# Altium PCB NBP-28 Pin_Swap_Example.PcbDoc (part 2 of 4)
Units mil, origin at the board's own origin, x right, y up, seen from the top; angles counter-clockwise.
Board outline 2716.54 x 4967.15 mil, 10 copper layers (Top Layer, Mid-Layer 1, VCC1V2, Mid-Layer 2, VCC, GND, MidLayer4, VCCINT, Mid-Layer 3, Bottom Layer), stack 81 mil thick; 254 components, 445 nets, 1667 pads, 770 vias.
Unrouted connection lines stored in the file: 611.
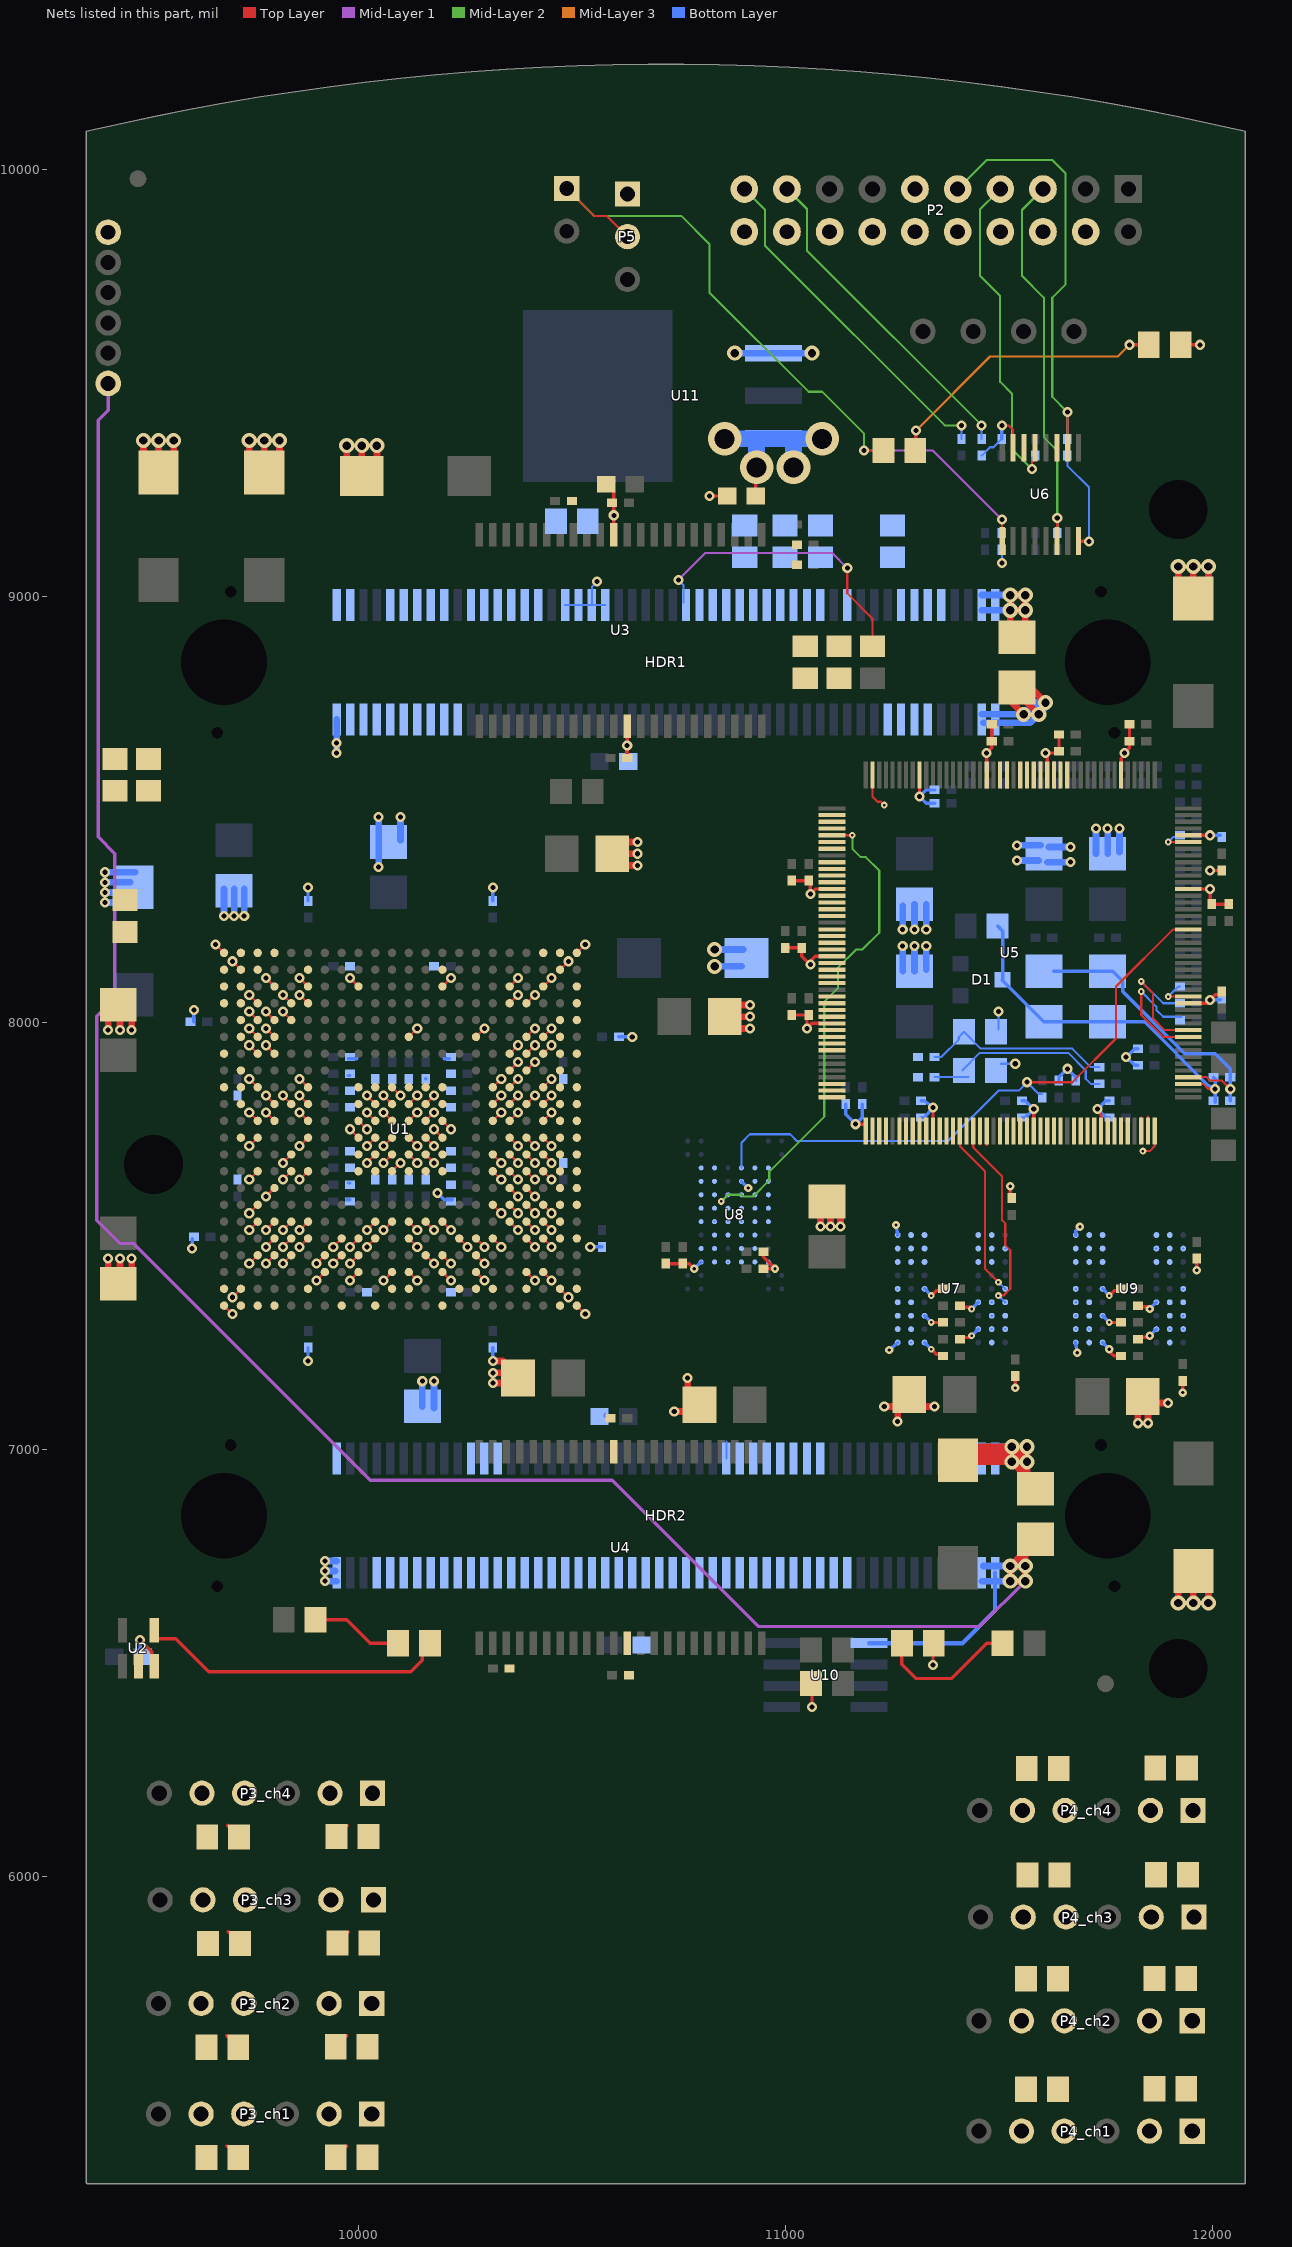
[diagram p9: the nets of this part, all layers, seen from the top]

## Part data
C1: library part CAP-NP-220nF-10V-0603, "Capacitor"
C2 C3 C16 C17 C30 C31 C32: library part CAP-P-10uF-16V-MCCT-B, "Polar Capacitor"
C4 C5 C12 C13 C14 C15 C18 C19 C20 C21 C33 C34 C35 C36 C41 C42: library part CAP-NP-0.1uF-16V-0402, "Capacitor"
C6 C7 C8 C9 C10 C11 C22 C23 C24 C25 C26 C27 C28 C29 C37 C38 C39 C40 C43 C44 C45 C46 C47 C48: library part CAP-NP-10nF-16V-0402, "Capacitor"
C49 C50 C64 C65 C66 C67 C88 C89 C102 C110 C111 C123 C125 C126 C127 C128 C129 C130 C131 C132 C133: library part CAP-P, "Polar Capacitor"
C51 C52 C53 C54 C55 C56 C57 C58 C59 C60 C61 C62 C63 C68 C69 C70 C71 C72 C73 C74 C75 C76 C77 C78 C79 C80 C81 C82 C83 C84 C85 C86 C87 C90 C91 C92 C93 C94 C95 C96 C97 C98 C99 C100 C101 C103 C104 C105 C106 C107 C108 C109 C112 C113 C114 C115 C116 C117 C118 C119 C120 C121 C122 C124: library part CAP-NP, "Capacitor"
D1: library part DIO-SCHOTTKY-1S-SOT23, "Schottky Barrier Double Diode"
HDR1 HDR2: library part CON-DOCKSTAT-M-0.8mm, "Board-to-Board, Docking Station, 0.80mm (.031\") Pitch, Shielded Receptacle, Vertical, Ultra Low Profile, SMT"
LED1: library part LED-RED-HSMHC170, "Typical GREEN SMD LED Agilent make"
LED2: library part LED-GRN-HSMHC170, "Typical GREEN SMD LED Agilent make"
LED3: library part DIO-LED-1S, "Typical GREEN SMD LED Agilent make"
P1: library part CON-HDR-1x2-STR, "Header, 2-Pin"
P2: library part CON-IDC-2x10-M-STR, "10x2 IDC Male PCB Box Header"
P3_ch1 P3_ch2 P3_ch3 P3_ch4 P4_ch1 P4_ch2 P4_ch3 P4_ch4: "Header, 6-Pin"
P5: "Header, 3-Pin"
R1 R15 R17 R18 R19: library part RES-4K7-0402, "Resistor"
R2 R3 R4 R6 R7 R8 R9 R10 R11 R12 R13 R14 R16: library part RES-100R-0805, "Resistor"
R5: library part RES-270R-1%-0805, "Resistor"
R20 R21 R22 R23 R24 R25 R26 R27 R28 R29 R30 R31 R32 R33 R34 R35 R36 R37 R38 R39 R40 R41 R42 R43 R44 R45 R46 R47 R48 R49 R50 R51 R52 R53 R54 R55 R56 R57 R58 R59 R60 R61 R62 R63 R64 R65 R66 R67 R68_ch1 R68_ch2 R68_ch3 R68_ch4 R69_ch1 R69_ch2 R69_ch3 R69_ch4 R70_ch1 R70_ch2 R70_ch3 R70_ch4 R71_ch1 R71_ch2 R71_ch3 R71_ch4: library part RES, "Resistor"
TP1 TP2 TP3 TP4 TP5 TP6 TP7 TP8 TP9 TP10: library part TestPin
U1: "Spartan-3 1.2V FPGA, 333 User I/Os, 456-ball FBGA, Standard Performance, Commercial Grade"
U3 U4: library part K6R4016V1D-T, "256Kx16Bit SRAM TSOP44"
U5: "32-Bit ARM720T-Based BlueStreak MCU with 8KB Cache, MMU, Color LCD controller, 32KB SRAM, 176-Pin LQFP"
U6: library part 74LCX157-TSOP16, "Quad 2-Input Multiplexer"
U7 U9: library part MT48LC16M16A2FG, "256Mb Synchronous High-Speed CMOS DRAM, 16Mb x 16Bit x 4 Banks, 54-Ball FPGA, Commercial"
U8: library part AM29LV640DU90RWHI, "64 Mb (4 M x 16) CMOS 3.0 Volt, Uniform Sector Flash Memory with VersatileI/O Control, 63-ball FBGA, Industrial Grade"
U10: library part VRG-ADJ-8, "Low Current 3-Terminal Adjustable Positive Voltage Regulator"
U11: library part VRG-ADJ-3, "5A Low Dropout Positive Regulators"

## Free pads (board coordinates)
  round 39.37 smd paste-39.37 mask+78.74: FID(9482.69,9978.67) FID(11750.41,6451.11)
  round 39.37 smd far side paste-39.37 mask+78.74: FID(9482.69,9978.67) FID(11750.41,6451.11)
  round 125.98 hole 137.8 unplated mask+3.94: LP(9519.16,7668.29) LP(11920.74,6487.18) LP(11920.74,9203.72)

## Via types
v1: diameter 23.62, hole 11.81, Top Layer to Bottom Layer, 495 vias
v2: diameter 78.74, hole 47.24, Top Layer to Bottom Layer, 101 vias
v3: diameter 15.75, hole 5.91, Top Layer to Bottom Layer, 92 vias
v4: diameter 35.43, hole 19.68, Top Layer to Bottom Layer, 59 vias
v5: diameter 19.68, hole 7.87, Top Layer to Bottom Layer, 23 vias

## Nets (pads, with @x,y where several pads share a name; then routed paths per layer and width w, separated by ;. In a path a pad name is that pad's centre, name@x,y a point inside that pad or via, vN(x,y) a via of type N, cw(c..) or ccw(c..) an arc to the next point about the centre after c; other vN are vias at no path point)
+5V: C123.1 C124.1 C125.1 HDR1.97 HDR1.99 HDR2.97 HDR2.99 TP8.1 U10.1 U11.3 | length 6499.5
  Top Layer w7.87: C124.1@10930.58,9235.22 v2@10930.58,9300.18
  Top Layer w15.75: C123.1@11530.97,8750.96 v4(11558.53,8723.41) ; C123.1@11546.72,8790.33 11546.72,8770.65 v4(11593.96,8723.41) ; C123.1@11558.53,8794.27 11566.41,8794.27 v4(11609.71,8750.96) ; C125.1@11562.47,6786.4 C125.1@11562.47,6762.78 ; v4(11527.04,6727.34) v4(11562.47,6727.34) ; v4(11527.04,6727.34) v4(11527.04,6691.91) v4(11562.47,6691.91) v4(11562.47,6727.34) ; v4(11527.04,6727.34) C125.1@11562.47,6762.78 ; v4(11562.47,6727.34) C125.1@11562.47,6762.78
  Mid-Layer 1 w7.87: TP8.1@9412.86,9499 9412.86,9436 9389.24,9412.38 9389.24,8436 9428.61,8396.63 9428.61,8058.05 9386.36,8015.81 9386.36,7537.3 9440.42,7483.25 9471.92,7483.25 10027.04,6928.13 10593.96,6928.13 10936.48,6585.61 11456.17,6585.61 v4(11562.47,6691.91)
  Bottom Layer w10: U10.1@11196.33,6546.44 11415,6546.44 11491.6,6623.04 11491.6,6691.91 HDR2.99@11491.6,6711.59
  Bottom Layer w15.75: HDR2.97@11460.11,6691.91 11491.6,6691.91 v4(11527.04,6691.91) v4(11562.47,6691.91) ; HDR1.97@11460.11,8723.41 v4(11558.53,8723.41) ; HDR2.97@11464.04,6727.34 v4(11527.04,6727.34) v4(11562.47,6727.34) ; HDR1.97@11464.04,8703.72 11574.28,8703.72 v4(11593.96,8723.41) ; v4@11586.09,8735.22 v4@11601.84,8750.96 ; v4(11558.53,8723.41) v4(11593.96,8723.41) ; v4(11558.53,8723.41) 11586.09,8750.96 v4@11601.84,8750.96 ; v4(11593.96,8723.41) 11609.71,8739.15 v4(11609.71,8750.96) v4@11601.84,8750.96
  Bottom Layer w39.37: v2(10857.74,9369.07) U11.3@10932.55,9369.07 ; v2(10932.55,9302.15) U11.3@10932.55,9369.07 ; v2(11019.16,9302.15) U11.3@11019.16,9369.07 ; v2(11086.09,9369.07) U11.3@11019.16,9369.07 ; U11.3@10932.55,9369.07 U11.3@11019.16,9369.07
A0: U1.H2 U5.32 U7.H7 U9.H7 | length 2.1
  Bottom Layer w5: U9.H7@11867.43,7471.44 U9.H7@11869.56,7471.44
A1: U1.R19 U5.31 U7.H8 U8.G2 U9.H8 | length 27.8
  Top Layer w5: U1.R19@10393.18,7613.17 v1(10412.86,7593.48)
A2: U1.P19 U5.30 U7.J8 U8.F2 U9.J8 | length 27.8
  Top Layer w5: U1.P19@10393.18,7652.54 v1(10412.86,7632.85)
A3: U1.N18 U5.29 U7.J7 U8.E2 U9.J7 | length 27.8
  Top Layer w5: U1.N18@10353.81,7691.91 v1(10373.49,7672.22)
A4: U1.K17 U5.27 U7.J3 U8.C2 U9.J3 | length 27.8
  Top Layer w5: U1.K17@10314.44,7810.02 v1(10334.12,7829.71)
A5: U1.N21 U5.26 U7.J2 U8.D2 U9.J2
A6: U1.P18 U5.25 U7.H3 U8.F3 U9.H3 | length 27.8
  Top Layer w5: U1.P18@10353.81,7652.54 v1(10373.49,7632.85)
A7: U1.P22 U5.24 U7.H2 U8.E3 U9.H2
A8: U1.L20 U5.22 U7.H1 U8.C3 U9.H1 | length 27.8
  Top Layer w5: U1.L20@10432.55,7770.65 v1(10452.23,7790.34)
A9: U1.N20 U5.21 U7.G3 U8.D6 U9.G3 | length 27.8
  Top Layer w5: U1.N20@10432.55,7691.91 v1(10452.23,7672.22)
A10: U1.K4 U5.20 U7.H9 U8.C6 U9.H9 | length 27.8
  Top Layer w5: v1(9782.94,7829.71) U1.K4@9802.63,7810.02
A11: U1.M2 U5.19 U7.G2 U8.E6 U9.G2
A12: U1.N5 U5.17 U7.G1 U8.F6 U9.G1 | length 27.8
  Top Layer w5: v1(9822.31,7672.22) U1.N5@9842,7691.91
A13: U1.N17 U5.16 U7.G7 U8.D7 U9.G7 | length 27.8
  Top Layer w5: U1.N17@10314.44,7691.91 v1(10334.12,7672.22)
A14: U1.N22 U5.15 U7.G8 U8.C7 U9.G8
A15: U1.M6 U5.14 U8.E7 | length 27.8
  Top Layer w5: v1(9861.68,7711.59) U1.M6@9881.37,7731.28
A16: U1.P17 U5.12 U8.F7 | length 27.8
  Top Layer w5: U1.P17@10314.44,7652.54 v1(10334.12,7632.85)
A17: U1.T19 U5.11 U8.G7 | length 27.8
  Top Layer w5: U1.T19@10393.18,7573.8 v1(10412.86,7554.11)
A18: U1.M18 U5.10 U8.D3 | length 27.8
  Top Layer w5: U1.M18@10353.81,7731.28 v1(10373.49,7711.59)
A19: U1.P21 U5.9 U8.E4
A20: U1.R21 U5.7 U8.F5
A21: U1.R22 U5.6 U8.F4
A22: U1.N19 U5.5 U8.E5 | length 1190.8
  Top Layer w5: U1.N19@10393.18,7691.91 v1(10412.86,7672.22) ; U5.5@11109.71,8439.94 v3(11156.96,8439.94)
  Mid-Layer 2 w5: v3(10849.87,7581.67) 10865.62,7597.42 10897.11,7597.42 10901.05,7593.48 10924.67,7593.48 10962.23,7631.04 10962.23,7651.45 11091.21,7780.43 11091.21,8049.6 11123.02,8081.41 11123.02,8129.48 11165.76,8172.22 11180.58,8172.22 11219.95,8211.59 11219.95,8357.26 11188.45,8388.76 11176.64,8388.76 11156.96,8408.44 v3(11156.96,8439.94)
  Bottom Layer w5: v3(10849.87,7581.67) U8.E5@10865.62,7597.42
A23: U1.F16 U5.4 | length 27.8
  Top Layer w5: U1.F16@10275.07,7967.5 v1(10294.75,7987.19)
A24: U1.D18 U5.3 | length 27.8
  Top Layer w5: U1.D18@10353.81,8046.24 v1(10373.49,8065.93)
A25: U1.F12 U5.2 | length 27.8
  Top Layer w5: U1.F12@10117.59,7967.5 v1(10137.27,7987.19)
AUDIO_SPI_CSN: HDR1.11 U1.F2
BLUE0: HDR1.14 U1.D3 | length 27.8
  Top Layer w5: v1(9743.57,8065.93) U1.D3@9763.26,8046.24
BLUE1: HDR1.16 U1.A4
BOC_CTS: HDR1.13 U1.F4 | length 27.8
  Top Layer w5: v1(9782.94,7987.19) U1.F4@9802.63,7967.5
BOC_RTS: HDR1.17 U1.E5 | length 27.8
  Top Layer w5: v1(9822.31,8026.56) U1.E5@9842,8006.87
BOC_RX: HDR1.19 U1.D6 | length 27.8
  Top Layer w5: v1(9861.68,8065.93) U1.D6@9881.37,8046.24
BOC_TX: HDR1.15 U1.D5 | length 27.8
  Top Layer w5: v1(9822.31,8065.93) U1.D5@9842,8046.24
BUZZER: HDR2.24 U1.W8 | length 27.8
  Top Layer w5: v1(9940.42,7436) U1.W8@9960.11,7455.69
CAN_RXD: HDR1.4 U1.D1
CAN_TXD: HDR1.2 U1.C1
CLK_RTC: R44.2 U1.J18 | length 27.8
  Top Layer w5: U1.J18@10353.81,7849.39 v1(10373.49,7869.08)
CLKIN: R36.2 U1.J17 | length 27.8
  Top Layer w5: U1.J17@10314.44,7849.39 v1(10334.12,7869.08)
CLKOUT: U1.D22 U5.156
D0: U1.R18 U5.87 U8.G3 U9.A8 | length 60.9
  Top Layer w5: U1.R18@10353.81,7613.17 v1(10373.49,7593.48) ; U5.87@11849.87,7747.03 11849.87,7780.13
D1: U1.V22 U5.86 U8.K3 U9.B9 | length 31.5
  Top Layer w5: U5.86@11834.12,7747.03 U5.86@11834.12,7778.52
D2: U1.T22 U5.84 U8.G4 U9.B8 | length 0
D3: U1.V21 U5.83 U8.K4 U9.C9 | length 0
D4: U1.U14 U5.82 U8.K5 U9.C8 | length 27.8
  Top Layer w5: U1.U14@10196.33,7534.43 v1(10216.01,7514.74)
D5: U1.T21 U5.81 U8.G5 U9.D9 | length 0
D6: U1.V20 U5.79 U8.K6 U9.D8 | length 27.8
  Top Layer w5: U1.V20@10432.55,7495.06 v1(10452.23,7475.37)
D7: U1.T20 U5.78 U8.G6 U9.E9 | length 27.8
  Top Layer w5: U1.T20@10432.55,7573.8 v1(10452.23,7554.11)
D8: U1.T18 U5.77 U8.H3 U9.E1 | length 27.8
  Top Layer w5: U1.T18@10353.81,7573.8 v1(10373.49,7554.11)
D9: U1.U20 U5.76 U8.J3 U9.D2 | length 27.8
  Top Layer w5: U1.U20@10432.55,7534.43 v1(10452.23,7514.74)
D10: U1.T17 U5.74 U8.H4 U9.D1 | length 27.8
  Top Layer w5: U1.T17@10314.44,7573.8 v1(10334.12,7554.11)
D11: U1.U19 U5.73 U8.J4 U9.C2 | length 27.8
  Top Layer w5: U1.U19@10393.18,7534.43 v1(10412.86,7514.74)
D12: U1.R4 U5.72 U8.H5 U9.C1 | length 27.8
  Top Layer w5: v1(9782.94,7593.48) U1.R4@9802.63,7613.17
D13: U1.P6 U5.71 U8.J6 U9.B2 | length 27.8
  Top Layer w5: v1(9861.68,7632.85) U1.P6@9881.37,7652.54
D14: U1.U21 U5.69 U8.H6 U9.B1 | length 0
D15: U1.U18 U5.68 U8.J7 U9.A2 | length 27.8
  Top Layer w5: U1.U18@10353.81,7534.43 v1(10373.49,7514.74)
D16: U1.K19 U5.67 U7.A8 | length 27.8
  Top Layer w5: U1.K19@10393.18,7810.02 v1(10412.86,7829.71)
D17: U1.M22 U5.66 U7.B9 | length 0
D18: U1.K22 U5.65 U7.B8 | length 0
D19: U1.M19 U5.63 U7.C9 | length 60.9
  Top Layer w5: U1.M19@10393.18,7731.28 v1(10412.86,7711.59) ; 11471.92,7713.93 U5.63@11471.92,7747.03
D20: U1.K21 U5.62 U7.C8 | length 31.5
  Top Layer w5: 11456.17,7715.53 U5.62@11456.17,7747.03
D21: U1.J2 U5.61 U7.D9 | length 462.3
  Top Layer w5: U5.61@11440.42,7747.03 11440.42,7708.38 11507.35,7641.45 11507.35,7538.37 11515.22,7530.49 11515.22,7479.31 11527.04,7467.5 11527.04,7376.95 11511.29,7361.2 v3(11499.48,7361.2)
  Bottom Layer w5: v3(11499.48,7361.2) U7.D9@11515.22,7345.45
D22: U1.K6 U5.60 U7.D8 | length 27.8
  Top Layer w5: v1(9861.68,7829.71) U1.K6@9881.37,7810.02
D23: U1.M20 U5.59 U7.E9 | length 441.9
  Top Layer w5: U1.M20@10432.55,7731.28 v1(10452.23,7711.59) ; U5.59@11408.93,7747.03 11408.93,7711.59 11467.98,7652.54 11467.98,7424.19 v3(11499.48,7392.7)
  Bottom Layer w5: v3(11499.48,7392.7) U7.E9@11515.22,7376.95
D24: U1.V19 U5.58 U7.E1 | length 27.8
  Top Layer w5: U1.V19@10393.18,7495.06 v1(10412.86,7475.37)
D25: U1.K5 U5.57 U7.D2 | length 27.8
  Top Layer w5: v1(9822.31,7829.71) U1.K5@9842,7810.02
D26: U1.K18 U5.56 U7.D1 | length 27.8
  Top Layer w5: U1.K18@10353.81,7810.02 v1(10373.49,7829.71)
D27: U1.L18 U5.54 U7.C2 | length 27.8
  Top Layer w5: U1.L18@10353.81,7770.65 v1(10373.49,7790.34)
D28: U1.L17 U5.53 U7.C1 | length 27.8
  Top Layer w5: U1.L17@10314.44,7770.65 v1(10334.12,7790.34)
D29: U1.K2 U5.52 U7.B2
D30: U1.M21 U5.51 U7.B1 | length 3.3
  Top Layer w5: U5.51@11280.64,7744.72 U5.51@11282.94,7747.03
D31: U1.L22 U5.50 U7.A2 | length 0
DEBUG_TCK: P2.9 R63.2 U6.10 | length 1026.9
  Top Layer w5: U6.10@11660.89,9349.39 v1(11660.89,9432.07)
  Mid-Layer 2 w5: P2.9@11403.81,9954.51 11471.92,10022.62 11625.46,10022.62 11656.96,9991.12 11656.96,9731.28 11625.46,9699.78 11625.46,9467.5 v1(11660.89,9432.07)
  Bottom Layer w5: R63.2@11660.89,9369.07 v1(11660.89,9432.07)
DEBUG_TDI: P2.5 R61.2 U6.6 | length 915.7
  Top Layer w5: U6.6@11637.27,9128.92 v1(11637.27,9184.04)
  Mid-Layer 2 w5: P2.5@11603.81,9954.51 11554.59,9905.3 11554.59,9750.96 11605.78,9699.78 11605.78,9373.01 11637.27,9341.52 v1(11637.27,9184.04)
  Bottom Layer w5: R61.2@11637.27,9148.6 v1(11637.27,9184.04)
DEBUG_TMS: P2.7 R62.2 U6.13 | length 768.8
  Top Layer w5: v1(11578.22,9298.21) 11578.22,9313.96 U6.13@11586.09,9321.83
  Mid-Layer 2 w5: P2.7@11495.18,9945.88 11456.17,9906.87 11456.17,9750.96 11503.41,9703.72 11503.41,9502.93 11530.97,9475.37 11530.97,9345.45 v1(11578.22,9298.21)
  Bottom Layer w5: v1(11578.22,9298.21) R62.2@11578.22,9325.77
DEOT0: U1.F21 U5.148
DIFF_RX_ch1_N: P3_ch1.5 P4_ch1.1 R69_ch1.2 R71_ch1.1
DIFF_RX_ch1_P: P3_ch1.4 P4_ch1.2 R69_ch1.1 R71_ch1.2 | length 38.7
  Top Layer w7.87: 9690.46,5368.14 R71_ch1.2@9717.86,5340.74
DIFF_RX_ch2_N: P3_ch2.5 P4_ch2.1 R69_ch2.2 R71_ch2.1
DIFF_RX_ch2_P: P3_ch2.4 P4_ch2.2 R69_ch2.1 R71_ch2.2 | length 38.7
  Top Layer w7.87: 9690.46,5626.94 R71_ch2.2@9717.86,5599.54
DIFF_RX_ch3_N: P3_ch3.5 P4_ch3.1 R69_ch3.2 R71_ch3.1
DIFF_RX_ch3_P: P3_ch3.4 P4_ch3.2 R69_ch3.1 R71_ch3.2 | length 38.7
  Top Layer w7.87: 9694.39,5869.98 R71_ch3.2@9721.79,5842.58
DIFF_RX_ch4_N: P3_ch4.5 P4_ch4.1 R69_ch4.2 R71_ch4.1
DIFF_RX_ch4_P: P3_ch4.4 P4_ch4.2 R69_ch4.1 R71_ch4.2 | length 38.7
  Top Layer w7.87: 9692.43,6119.92 R71_ch4.2@9719.83,6092.52
DIFF_TX_ch1_N: P3_ch1.2 P4_ch1.5 R68_ch1.1 R70_ch1.1 | length 36.3
  Top Layer w7.87: R70_ch1.1@9946.13,5341.73 9971.82,5367.42
DIFF_TX_ch1_P: P3_ch1.1 P4_ch1.4 R68_ch1.2 R70_ch1.2
DIFF_TX_ch2_N: P3_ch2.2 P4_ch2.5 R68_ch2.1 R70_ch2.1 | length 36.3
  Top Layer w7.87: R70_ch2.1@9946.13,5600.52 9971.82,5626.22
DIFF_TX_ch2_P: P3_ch2.1 P4_ch2.4 R68_ch2.2 R70_ch2.2
DIFF_TX_ch3_N: P3_ch3.2 P4_ch3.5 R68_ch3.1 R70_ch3.1 | length 36.3
  Top Layer w7.87: R70_ch3.1@9950.06,5843.57 9975.76,5869.26
DIFF_TX_ch3_P: P3_ch3.1 P4_ch3.4 R68_ch3.2 R70_ch3.2
DIFF_TX_ch4_N: P3_ch4.2 P4_ch4.5 R68_ch4.1 R70_ch4.1 | length 36.3
  Top Layer w7.87: R70_ch4.1@9948.09,6093.5 9973.79,6119.2
DIFF_TX_ch4_P: P3_ch4.1 P4_ch4.4 R68_ch4.2 R70_ch4.2
DREQ0: U1.G21 U5.146
FLASH_BUSY: R20.1 U5.114 U8.C4 | length 1444.8
  Top Layer w5: v1(11566.41,7861.2) 11672.7,7861.2 11775.07,7963.56 11775.07,8085.61 11908.93,8219.47 U5.114@11944.36,8219.47
  Bottom Layer w5: U8.C4@10897.11,7660.41 10897.11,7719.47 10916.8,7739.15 11011.29,7739.15 11027.04,7723.41 11381.37,7723.41 11499.48,7841.52 11546.72,7841.52 v1(11566.41,7861.2) 11593.96,7833.64 R20.1@11601.84,7833.64
FPGA_AUX0: R14.1 U1.B3
FPGA_AUX0_R: HDR1.86 R14.2
FPGA_AUX1: HDR1.88 U1.C18 | length 27.8
  Top Layer w5: U1.C18@10353.81,8085.61 v1(10373.49,8105.3)
FPGA_AUX2: HDR1.90 U1.C20 | length 27.8
  Top Layer w5: U1.C20@10432.55,8085.61 v1(10452.23,8105.3)
FPGA_AUX3: HDR1.92 U1.D19 | length 27.8
  Top Layer w5: U1.D19@10393.18,8046.24 v1(10412.86,8065.93)
FPGA_CCLK: R3.2 U1.AA22
FPGA_CCLK_R: HDR1.66 R3.1
FPGA_CLK: HDR2.2 U1.AA11
FPGA_CLK_1: HDR1.30 U1.F3 | length 27.8
  Top Layer w5: v1(9743.57,7987.19) U1.F3@9763.26,7967.5
FPGA_CLK_2: HDR1.32 U1.G4 | length 27.8
  Top Layer w5: v1(9782.94,7947.82) U1.G4@9802.63,7928.13
FPGA_DIN: HDR1.64 U1.B14
FPGA_DONE: R4.2 R15.1 U1.AB21 U2.2
FPGA_DONE_R: HDR1.74 R4.1
FPGA_INIT: HDR1.68 R18.1 R19.1
FPGA_M0: R8.2 U1.AB2
FPGA_M0_R: HDR1.60 R8.1
FPGA_M1: R9.2 U1.AA1
FPGA_M1_R: HDR1.58 R9.1
FPGA_M2: R10.2 U1.AB3
FPGA_M2_R: HDR1.56 R10.1
FPGA_PROGRAM_R: HDR1.62 R7.1 R17.1
FPGA_PROGRAMP: R7.2 U1.A2
FPGA_TCK: HDR1.72 R12.1 U6.11
FPGA_TCKP: R12.2 U1.A21
FPGA_TDI: HDR1.78 R11.1
FPGA_TDIP: R11.2 U1.B1
FPGA_TDO: HDR1.54 R6.2 | length 702.1
  Top Layer w5: v1(11145.15,9065.92) 11145.15,9006.87 11204.2,8947.81 R6.2@11204.2,8882.85
  Mid-Layer 1 w5: v1(10749.3,9038.31) 10812.34,9101.36 11109.71,9101.36 v1(11145.15,9065.92)
  Bottom Layer w5: v1(10749.3,9038.31) 10761.3,9026.31 HDR1.54@10761.3,8985.31
FPGA_TMS: HDR1.70 R13.1 U6.14
FPGA_TMSP: R13.2 U1.A20
GND: C1.1 C2.2 C3.2 C4.2 C5.2 C6.2 C7.2 C8.2 C9.2 C10.2 C11.2 C12.2 C13.2 C14.2 C15.2 C16.2 C17.2 C18.2 C19.2 C20.2 C21.2 C22.2 C23.2 C24.2 C25.2 C26.2 C27.2 C28.2 C29.2 C30.2 C31.2 C32.2 C33.2 C34.2 C35.2 C36.2 C37.2 C38.2 C39.2 C40.2 C41.2 C42.2 C43.2 C44.2 C45.2 C46.2 C47.2 C48.2 C49.2 C50.2 C51.2 C52.2 C53.2 C54.2 C55.2 C56.2 C57.2 C58.2 C62.2 C66.2 C67.2 C68.2 C69.2 C70.2 C71.2 C72.2 C73.2 C74.2 C75.2 C76.2 C77.2 C78.2 C79.2 C80.2 C81.2 C82.2 C83.2 C84.2 C85.2 C86.2 C87.2 C88.2 C89.2 C90.2 C91.2 C92.2 C93.2 C94.2 C95.2 C96.2 C97.2 C98.2 C99.2 C100.2 C101.2 C102.2 C103.2 C104.2 C105.2 C106.2 C107.2 C108.2 C109.2 C110.2 C111.2 C112.2 C113.2 C114.2 C115.2 C116.2 C117.2 C118.2 C119.2 C120.2 C121.2 C122.2 C123.2 C124.2 C125.2 C126.2 C127.2 C128.2 C129.2 C130.2 C131.2 C132.2 C133.2 HDR1.1 HDR1.36 HDR1.38 HDR1.40 HDR1.42 HDR1.98 HDR1.100 HDR2.1 HDR2.98 HDR2.100 LED1.2 LED3.2 P2.4 P2.6 P2.8 P2.10 P2.11 P2.12 P2.14 P2.16 P2.18 P2.20 P5.1 R37.1 R46.1 R60.2 R63.1 R65.2 R66.1 TP10.1 U1.A1 U1.A22 U1.AA2 U1.AA21 U1.AB1 U1.AB22 U1.B2 U1.B21 U1.C9 U1.C14 U1.J3 U1.J9 U1.J10 U1.J11 U1.J12 U1.J13 U1.J14 U1.J20 U1.K9 U1.K10 U1.K11 U1.K12 U1.K13 U1.K14 U1.L9 U1.L10 U1.L11 U1.L12 U1.L13 U1.L14 U1.M9 U1.M10 U1.M11 U1.M12 U1.M13 U1.M14 U1.N9 U1.N10 U1.N11 U1.N12 U1.N13 U1.N14 U1.P3 U1.P9 U1.P10 U1.P11 U1.P12 U1.P13 U1.P14 U1.P20 U1.Y9 U1.Y14 U2.3 U3.12 U3.34 U4.12 U4.34 U5.13 U5.23 U5.33 U5.45 U5.55 U5.70 U5.80 U5.88 U5.103 U5.120 U5.128 U5.138 U5.149 U5.158 U5.168 U5.175 U6.8 U6.15 U7.A1 U7.A3 U7.B7 U7.C3 U7.D7 U7.E3 U7.J1 U8.D4 U8.K2 U8.K7 U9.A1 U9.A3 U9.B7 U9.C3 U9.D7 U9.E3 U9.J1 U11.1 | length 11663.4
  Top Layer w5: v1(9664.83,8184.04) U1.A1@9684.52,8164.35 ; U1.AB1@9684.52,7337.58 v1(9704.2,7317.89) ; v1(9704.2,7357.26) U1.AA2@9723.89,7376.95 ; v1(9704.2,8144.67) U1.B2@9723.89,8124.98 ; v1(9743.57,7632.85) U1.P3@9763.26,7652.54 ; v1(9743.57,7869.08) U1.J3@9763.26,7849.39 ; v1(9979.79,7396.63) U1.Y9@9999.48,7416.32 ; v1(9979.79,7750.97) U1.M9@9999.48,7731.28 ; v1(9979.79,8105.3) U1.C9@9999.48,8085.61 ; U1.L9@9999.48,7770.65 v1(10019.16,7750.96) ; v1(10019.16,7672.22) U1.N10@10038.85,7691.91 ; v1(10019.16,7711.59) U1.M10@10038.85,7731.28 ; v1(10019.16,7790.34) U1.L10@10038.85,7770.65 ; v1(10019.16,7829.71) U1.K10@10038.85,7810.02 ; v1(10058.53,7672.22) U1.N11@10078.22,7691.91 ; v1(10058.53,7711.59) U1.M11@10078.22,7731.28 ; v1(10058.53,7790.34) U1.L11@10078.22,7770.65 ; v1(10058.53,7829.71) U1.K11@10078.22,7810.02 ; U1.P11@10078.22,7652.54 v1(10097.9,7672.23) ; U1.J11@10078.22,7849.39 v1(10097.9,7829.7) ; U1.N12@10117.59,7691.91 v1(10137.27,7672.22) ; U1.M12@10117.59,7731.28 v1(10137.27,7711.59) ; U1.L12@10117.59,7770.65 v1(10137.27,7790.34) ; U1.K12@10117.59,7810.02 v1(10137.27,7829.71) ; U1.N13@10156.96,7691.91 v1(10176.64,7672.22) ; U1.M13@10156.96,7731.28 v1(10176.64,7711.59) ; U1.L13@10156.96,7770.65 v1(10176.64,7790.34) ; U1.K13@10156.96,7810.02 v1(10176.64,7829.71) ; v1(10176.64,7750.97) U1.M14@10196.33,7731.28 ; U1.Y14@10196.33,7416.32 v1(10216.01,7396.63) ; U1.L14@10196.33,7770.65 v1(10216.01,7750.96) ; U1.C14@10196.33,8085.61 v1(10216.01,8105.3) ; U1.P20@10432.55,7652.54 v1(10452.23,7632.85) ; U1.J20@10432.55,7849.39 v1(10452.23,7869.08) ; U1.AA21@10471.92,7376.95 v1(10491.6,7357.26) ; U1.B21@10471.92,8124.98 v1(10491.6,8144.67) ; U1.AB22@10511.29,7337.58 v1(10530.97,7317.89) ; U1.A22@10511.29,8164.35 v1(10530.97,8184.04) ; U5.175@11204.2,8581.67 11204.2,8530.49 11216.01,8518.68 11223.89,8518.68 v3(11231.76,8510.81) ; v1(11507.35,9400.57) 11523.1,9400.57 11533.93,9389.74 U6.15@11533.93,9348.41 ; v3(11838.06,7699.78) 11853.81,7699.78 11865.62,7711.59 U5.88@11865.62,7747.03
  Top Layer w7.87: v1(9487.67,6554.11) 9515.22,6526.55 U2.3@9515.22,6495.06 ; U3.34@10597.9,9139.74 v1(10597.9,9189.94) 10597.9,9262.78 C51.2@10597.9,9270.65 ; C53.2@10629.4,8621.04 v1(10629.4,8650.57) U3.12@10629.4,8695.85 U3.12@10629.4,8700.77 ; C105.2@10719.95,7436 10775.07,7436 v5(10786.88,7424.19) ; v1(10822.31,9235.22) C124.2@10863.65,9235.22 ; C103.2@10948.3,7424.19 v5(10975.85,7424.19) 10948.3,7451.75 C106.2@10948.3,7463.56 ; C71.2@10999.48,8176.16 C81.2@11038.85,8176.16 11038.85,8156.48 v1(11058.53,8136.79) 11058.53,8144.67 11070.34,8156.48 U5.23@11109.71,8156.48 ; C70.2@11015.22,8018.68 C80.2@11054.59,8018.68 ; C68.2@11015.22,8333.64 C78.2@11054.59,8333.64 ; C80.2@11058.53,8014.74 11054.6,8014.74 11050.66,8014.74 v1(11050.66,7987.18) 11062.47,7999 U5.33@11109.71,7999 ; C78.2@11058.53,8329.7 v1(11058.53,8302.15) 11070.34,8313.96 U5.13@11109.71,8313.96 ; v1(11062.47,6396.63) R65.2@11062.47,6449.78 ; v1(11164.83,7762.78) U5.45@11188.45,7762.78 ; v1(11314.44,8530.49) U5.168@11314.44,8581.67 ; v3(11342,7235.22) 11353.81,7223.41 C120.2@11373.49,7223.41 ; v3(11342,7298.21) C118.2@11369.56,7298.21 ; v3(11342,7361.2) 11353.81,7373.01 C109.2@11373.49,7373.01 ; v1(11345.93,6495.06) LED1.2@11345.93,6544.27 ; U5.55@11345.93,7747.03 v1(11345.93,7802.15) ; C119.2@11404.99,7262.78 11432.55,7262.78 v3(11436.48,7266.71) ; C121.2@11404.99,7333.64 11432.55,7333.64 v3(11436.48,7329.7) ; U5.158@11471.92,8581.67 v1(11471.92,8632.85) 11483.73,8644.67 C95.2@11483.73,8699.78 ; C122.2@11527.04,7593.48 v5(11527.04,7617.11) ; v5(11538.85,7144.67) C108.2@11538.85,7172.22 ; U5.70@11582.15,7747.03 v1(11582.15,7798.21) ; v1(11609.71,8632.85) C86.2@11637.27,8632.85 ; U5.149@11613.65,8581.67 v1@11613.65,8628.92 ; C86.2@11641.21,8636.79 C76.2@11641.21,8676.16 ; U6.8@11688.45,9128.92 v1(11712.08,9128.92) ; v1@11731.76,7794.27 11739.63,7786.4 U5.80@11739.63,7747.03 ; v5@11758.33,7232.28 11770.14,7220.47 C117.2@11789.82,7220.47 ; v3(11759.32,7298.21) C112.2@11786.88,7298.21 ; v3(11759.32,7361.2) 11771.13,7373.01 C107.2@11790.82,7373.01 ; U5.138@11786.88,8581.67 11786.88,8621.04 v1@11794.75,8628.92 ; v1(11794.75,8632.85) 11806.56,8644.67 C94.2@11806.56,8699.78 ; C115.2@11821.32,7263.78 11848.88,7263.78 v5@11852.81,7267.71 ; C116.2@11821.32,7334.64 11848.88,7334.64 v5@11852.82,7330.7 ; LED3.2@11926.64,9589.55 v1(11971.92,9589.55) ; v5(11931.56,7133.85) C114.2@11931.56,7161.41 ; U5.103@11944.36,8046.24 11987.67,8046.24 v1(11995.54,8054.11) 12007.35,8065.93 C84.2@12023.1,8065.93 ; U5.120@11944.36,8313.96 v1(11995.54,8313.96) C101.2@11995.54,8282.46 ; U5.128@11944.36,8439.94 v1(11995.54,8439.94) ; v5(11964.04,7420.26) C113.2@11964.04,7447.81 ; v1(11995.54,8357.26) C75.2@12023.1,8357.26 ; C101.2@11999.48,8278.52 C93.2@12038.85,8278.52
  Top Layer w15.75: C3.2@9404.99,7384.82 9412.86,7388.76 v1(9412.86,7447.81) ; C32.2@9404.99,8046.24 9412.86,8042.3 v1(9412.86,7983.25) ; C3.2@9436.48,7384.82 9440.42,7388.76 v1(9440.42,7447.81) ; C32.2@9436.48,8046.24 9440.42,8042.3 v1(9440.42,7983.25) ; C3.2@9467.98,7384.82 v1(9467.98,7447.81) ; v1(9467.98,7983.25) C32.2@9467.98,8046.24 ; C130.2@9495.54,9294.27 v4(9495.54,9365.14) ; C130.2@9530.97,9290.33 v4(9530.97,9365.14) ; C130.2@9566.41,9286.4 v4(9566.41,9365.14) ; C127.2@9743.57,9302.15 v4(9743.57,9365.14) ; C127.2@9779,9290.33 v4(9779,9365.14) ; C127.2@9814.44,9306.08 v4(9814.44,9365.14) ; C131.2@9971.92,9282.46 v4(9971.92,9353.33) ; C131.2@10007.35,9282.46 v4(10007.35,9353.33) ; C131.2@10042.78,9282.46 v4(10042.78,9353.33) ; v1(10314.44,7156.48) C2.2@10373.49,7156.48 ; v1(10314.44,7180.1) C2.2@10377.43,7180.1 ; v1(10314.44,7207.66) 10338.06,7207.66 C2.2@10357.74,7187.97 ; C49.2@10590.03,8369.07 v1(10653.02,8369.07) ; C49.2@10590.03,8424.19 v1(10653.02,8424.19) ; C49.2@10593.96,8396.63 v1(10653.02,8396.63) ; v1(10739.63,7089.55) C50.2@10802.63,7089.55 ; C50.2@10771.13,7093.48 v1(10771.13,7168.29) ; C31.2@10853.81,7987.18 v1(10916.8,7987.18) ; C31.2@10853.81,8042.3 v1(10916.8,8042.3) ; C31.2@10857.74,8014.74 v1(10916.8,8014.74) ; v1(11082.15,7522.62) C102.2@11082.15,7565.93 ; v1(11105.78,7522.62) C102.2@11105.78,7573.8 ; v1(11129.4,7522.62) C102.2@11129.4,7581.67 ; v1(11231.76,7101.36) C110.2@11263.26,7101.36 ; v1(11263.26,7065.93) C110.2@11263.26,7101.36 ; C110.2@11263.26,7113.17 C110.2@11263.26,7101.36 ; C110.2@11279,7101.36 C110.2@11263.26,7101.36 ; C110.2@11298.69,7101.36 v1(11349.87,7101.36) ; C132.2@11404.99,7006.87 v4(11530.97,7006.87) ; C132.2@11408.93,6971.44 v4(11530.97,6971.44) ; C132.2@11432.55,6995.06 v4@11530.97,6995.06 ; C132.2@11440.42,6983.25 v4@11530.97,6983.25 ; C123.2@11527.04,8896.63 v4(11527.04,8967.5) ; C123.2@11562.47,8896.63 v4(11562.47,8967.5) ; C125.2@11566.41,6912.38 C125.2@11566.41,6936 ; C125.2@11570.34,6932.07 C125.2@11566.41,6936 ; v1(11826.25,7061.99) C111.2@11826.25,7124.98 ; v1(11849.87,7061.99) C111.2@11849.87,7117.11 ; C111.2@11853.81,7109.23 v1(11897.11,7109.23) ; v4(11920.74,6640.73) C126.2@11920.74,6703.72 ; C133.2@11920.74,9006.87 v4(11920.74,9069.86) ; v4(11956.17,6640.73) C126.2@11956.17,6707.66 ; C133.2@11956.17,8995.06 v4(11956.17,9069.86) ; v4(11991.6,6640.73) C126.2@11991.6,6691.91 ; C133.2@11991.6,8991.12 v4(11991.6,9069.86) ; v4(11527.04,8967.5) v4(11562.47,8967.5) ; v4(11527.04,8967.5) v4(11527.04,9002.93) v4(11562.47,9002.93) v4(11562.47,8967.5) ; v4(11530.97,6971.44) v4(11566.41,6971.44) ; v4(11530.97,6971.44) v4@11530.97,6983.25 ; v4(11530.97,6971.44) C125.2@11566.41,6936 ; v4@11530.97,6983.25 v4@11530.97,6995.06 ; v4@11530.97,6983.25 11554.59,6983.25 v4(11566.41,6971.44) ; v4@11530.97,6995.06 v4(11530.97,7006.87) ; v4@11530.97,6995.06 11554.59,6995.06 v4(11566.41,7006.87) ; v4(11530.97,7006.87) v4(11566.41,7006.87) ; C125.2@11566.41,6936 v4(11566.41,6971.44) ; v4(11566.41,6971.44) v4(11566.41,7006.87)
  Bottom Layer w5: HDR1.36@10483.73,8979.31 HDR1.38@10515.22,8979.31 HDR1.40@10546.72,8979.31 ; v1(10558.53,9034.43) 10546.72,9022.62 HDR1.40@10546.72,8979.31 ; HDR1.42@10578.22,8979.31 HDR1.40@10546.72,8979.31 ; R66.1@11460.11,9329.7 11479.79,9349.39 11487.67,9349.39 C62.2@11507.35,9369.07 ; R37.1@11499.48,7985.22 v1(11499.48,8026.55) ; R46.1@11505.38,7904.51 v1(11538.85,7904.51) ; v1(11507.35,9077.74) R60.2@11507.35,9109.23 ; R63.1@11660.89,9329.7 11660.89,9306.08 11712.08,9254.9 v1(11712.08,9128.92)
  Bottom Layer w7.87: C1.1@9487.67,6516.71 v1(9487.67,6554.11) ; v1(9609.71,7471.44) C11.2@9609.71,7495.06 ; C9.2@9613.65,8002.93 v1(9613.65,8030.49) ; v1(9881.37,7207.66) C10.2@9881.37,7239.15 ; C4.2@9881.37,8286.4 v1(9881.37,8317.89) ; C24.2@9971.92,7585.61 C24.2@9979.79,7585.61 ; C20.2@9975.85,7624.98 C20.2@9979.79,7624.98 ; C21.2@9975.85,7876.95 C21.2@9979.79,7876.95 ; C22.2@9975.85,7916.32 9995.54,7916.32 ; v1(10184.52,7601.36) 10200.26,7585.61 C26.2@10219.95,7585.61 ; 10200.26,7916.32 C28.2@10212.08,7916.32 ; v1(10314.44,7207.66) C5.2@10314.44,7239.15 ; C8.2@10314.44,8286.4 v1(10314.44,8317.89) ; v1(10542.78,7475.37) C7.2@10570.34,7475.37 ; C56.2@10578.22,7077.74 C56.2@10578.22,7081.67 ; C6.2@10609.71,7967.5 v1(10641.21,7967.5) ; C52.2@10629.4,8615.14 v1(10629.4,8650.57) ; v5(10786.88,7424.19) U8.K7@10802.63,7439.94 ; U8.D4@10897.11,7628.92 v5(10912.86,7613.17) ; U8.K2@10960.11,7439.94 v5(10975.85,7424.19) ; C97.2@11141.21,7810.02 11141.21,7786.4 v1(11164.83,7762.78) 11180.58,7778.52 C92.2@11180.58,7810.02 ; v5(11243.36,7233.59) U7.A1@11263.26,7250.96 ; v5(11259.32,7526.55) U7.J1@11263.26,7502.93 ; C79.2@11318.37,7778.52 11326.25,7778.52 v1(11345.93,7802.15) 11326.25,7817.89 C69.2@11318.37,7817.89 ; U7.A3@11326.25,7250.96 v3(11342,7235.22) ; U7.C3@11326.25,7313.96 v3(11342,7298.21) ; U7.E3@11326.25,7376.95 v3(11342,7361.2) ; C87.2@11349.87,8514.74 11330.19,8514.74 v1(11314.44,8530.49) 11330.19,8546.24 C77.2@11349.87,8546.24 ; v3(11436.48,7266.71) U7.B7@11452.23,7282.46 ; v3(11436.48,7329.7) U7.D7@11452.23,7345.45 ; C62.2@11507.35,9369.07 v1(11507.35,9400.57) ; C83.2@11554.59,7778.52 11562.47,7778.52 v1(11582.15,7798.21) 11562.47,7817.89 C73.2@11554.59,7817.89 ; C98.2@11641.21,7865.14 11641.21,7873.01 v1(11660.89,7892.7) 11680.58,7873.01 C91.2@11680.58,7865.14 ; U9.A1@11679.59,7251.96 11679.59,7250.96 11679.63,7250.77 v5(11684.52,7227.34) ; U9.J1@11680.58,7502.93 11680.58,7512.78 v5(11690.42,7522.62) ; U9.A3@11743.57,7250.96 v5(11759.32,7235.22) ; U9.C3@11743.57,7313.96 v3(11759.32,7298.21) ; U9.E3@11743.57,7376.95 v3(11759.32,7361.2) ; C82.2@11759.32,7778.52 11751.45,7778.52 v1(11731.76,7798.21) 11751.45,7817.89 C72.2@11759.32,7817.89 ; C99.2@11826.25,7900.57 11818.37,7900.57 v1(11798.69,7920.26) 11818.37,7939.94 C90.2@11826.25,7939.94 ; v5(11853.81,7266.71) U9.B7@11869.56,7282.46 ; v5(11853.81,7329.7) U9.D7@11869.56,7345.45 ; v1(11995.54,8054.11) C74.2@12019.16,8054.11 ; v1(11995.54,8439.94) C85.2@12019.16,8439.94
  Bottom Layer w15.75: v1(9404.99,8282.46) C128.2@9460.11,8282.46 ; v1(9404.99,8306.08) C128.2@9460.11,8306.08 ; v1(9404.99,8329.7) C128.2@9464.04,8329.7 ; v1(9404.99,8353.33) C128.2@9475.85,8353.33 ; v1(9684.52,8250.96) C30.2@9684.52,8313.96 ; v1(9708.14,8250.96) C30.2@9708.14,8310.02 C30.2@9708.14,8313.96 ; v1(9731.76,8250.96) C30.2@9731.76,8313.96 ; v1(9920.74,6691.91) HDR2.1@9948.3,6691.91 ; v1(9920.74,6715.53) HDR2.1@9944.36,6715.53 ; v1(9920.74,6739.15) HDR2.1@9948.3,6739.15 ; v1(9948.3,8632.85) v1(9948.3,8656.48) HDR1.1@9948.29,8711.59 ; v1(10046.72,8365.14) v1(10046.72,8483.25) ; C17.2@10097.9,8428.13 v1(10097.9,8483.25) ; C16.2@10149.08,7101.36 v1(10149.08,7160.41) ; C16.2@10176.64,7097.42 v1(10176.64,7160.41) ; v4(10834.12,8132.85) C129.2@10897.11,8132.85 ; v4(10834.12,8172.22) C129.2@10901.05,8172.22 ; v4(10881.37,9569.86) U11.1@10971.92,9569.86 v4(11062.47,9569.86) ; C88.2@11275.07,8121.04 v1(11275.07,8180.1) ; v1(11275.07,8219.47) C67.2@11275.07,8274.59 ; C88.2@11302.63,8121.04 v1(11302.63,8180.1) ; v1(11302.63,8219.47) C67.2@11302.63,8278.52 ; C88.2@11330.19,8124.98 v1(11330.19,8180.1) ; v1(11330.19,8219.47) C67.2@11330.19,8278.52 ; HDR2.98@11460.11,6971.44 v4(11530.97,6971.44) v4(11566.41,6971.44) ; HDR2.98@11460.11,7006.87 11491.6,7006.87 v4(11530.97,7006.87) v4(11566.41,7006.87) ; HDR1.98@11460.11,8967.5 v4(11527.04,8967.5) ; HDR1.98@11460.11,9002.93 v4(11527.04,9002.93) ; v1(11542.78,8380.89) C89.2@11593.96,8380.89 ; v1(11542.78,8416.32) C89.2@11597.9,8416.32 ; C89.2@11613.65,8376.95 v1(11668.77,8376.95) ; C89.2@11617.59,8412.38 v1(11668.77,8412.38) ; C66.2@11727.82,8396.63 v1(11727.82,8455.69) ; C66.2@11755.38,8396.63 v1(11755.38,8455.69) ; C66.2@11782.94,8400.57 v1(11782.94,8455.69) ; v4(11527.04,8967.5) v4(11562.47,8967.5) v4(11562.47,9002.93) v4(11527.04,9002.93) ; v4(11527.04,8967.5) v4(11527.04,9002.93)
GREEN0: HDR1.10 U1.C2
GREEN1: HDR1.12 U1.D2
HDRIVE: HDR1.18 U1.E3 | length 27.8
  Top Layer w5: v1(9743.57,8026.56) U1.E3@9763.26,8006.87
INT0: U1.F19 U5.155 | length 27.8
  Top Layer w5: U1.F19@10393.18,7967.5 v1(10412.86,7987.19)
INT1: U1.E21 U5.153
INT2: U1.G18 U5.152 | length 27.8
  Top Layer w5: U1.G18@10353.81,7928.13 v1(10373.49,7947.82)
INT3: U1.F20 U5.151 | length 27.8
  Top Layer w5: U1.F20@10432.55,7967.5 v1(10452.23,7987.19)
INT4: U1.E22 U5.150
IO0: HDR2.7 U1.W3 | length 27.8
  Top Layer w5: v1(9743.57,7436) U1.W3@9763.26,7455.69
IO1: HDR2.9 U1.AB4
IO2: HDR2.11 U1.W4 | length 27.8
  Top Layer w5: v1(9782.94,7436) U1.W4@9802.63,7455.69
IO3: HDR2.13 U1.T3 | length 27.8
  Top Layer w5: v1(9743.57,7554.11) U1.T3@9763.26,7573.8
IO4: HDR2.15 U1.U3 | length 27.8
  Top Layer w5: v1(9743.57,7514.74) U1.U3@9763.26,7534.43
IO5: HDR2.17 U1.V4 | length 27.8
  Top Layer w5: v1(9782.94,7475.37) U1.V4@9802.63,7495.06
IO6: HDR2.19 U1.W5 | length 27.8
  Top Layer w5: v1(9822.31,7436) U1.W5@9842,7455.69
IO7: HDR2.21 U1.U4 | length 27.8
  Top Layer w5: v1(9782.94,7514.74) U1.U4@9802.63,7534.43
IO8: HDR2.23 U1.AA6
IO9: HDR2.25 U1.V5 | length 27.8
  Top Layer w5: v1(9822.31,7475.37) U1.V5@9842,7495.06
IO10: HDR2.27 U1.Y7 | length 27.8
  Top Layer w5: v1(9901.05,7396.63) U1.Y7@9920.74,7416.32
IO11: HDR2.29 U1.AB8
IO12: HDR2.31 U1.V6 | length 27.8
  Top Layer w5: v1(9861.68,7475.37) U1.V6@9881.37,7495.06
IO13: HDR2.33 U1.U5 | length 27.8
  Top Layer w5: v1(9822.31,7514.74) U1.U5@9842,7534.43
IO14: HDR2.35 U1.U6 | length 27.8
  Top Layer w5: v1(9861.68,7514.74) U1.U6@9881.37,7534.43
IO15: HDR2.37 U1.AB10
IO16: HDR2.39 U1.V8 | length 27.8
  Top Layer w5: v1(9940.42,7475.37) U1.V8@9960.11,7495.06
IO17: HDR2.41 U1.W9 | length 27.8
  Top Layer w5: v1(9979.79,7436) U1.W9@9999.48,7455.69
IO18: HDR2.43 U1.P5 | length 27.8
  Top Layer w5: v1(9822.31,7632.85) U1.P5@9842,7652.54
IO19: HDR2.45 U1.V9 | length 27.8
  Top Layer w5: v1(9979.79,7475.37) U1.V9@9999.48,7495.06
IO20: HDR2.47 U1.Y11 | length 27.8
  Top Layer w5: v1(10058.53,7396.63) U1.Y11@10078.22,7416.32
IO21: HDR2.49 U1.V10 | length 27.8
  Top Layer w5: v1(10019.16,7475.37) U1.V10@10038.85,7495.06
IO22: HDR2.51 U1.AA12
IO23: HDR2.53 U1.U10 | length 27.8
  Top Layer w5: v1(10019.16,7514.74) U1.U10@10038.85,7534.43
IO24: HDR2.55 U1.Y12 | length 27.8
  Top Layer w5: U1.Y12@10117.59,7416.32 v1(10137.27,7396.63)
IO25: HDR2.57 U1.AB14
IO26: HDR2.59 U1.AA15
IO27: HDR2.61 U1.U11 | length 27.8
  Top Layer w5: v1(10058.53,7514.74) U1.U11@10078.22,7534.43
IO28: HDR2.63 U1.W13 | length 27.8
  Top Layer w5: U1.W13@10156.96,7455.69 v1(10176.64,7436)
IO29: HDR2.65 U1.V12 | length 27.8
  Top Layer w5: U1.V12@10117.59,7495.06 v1(10137.27,7475.37)
IO30: HDR2.67 U1.AA16
IO31: HDR2.69 U1.W14 | length 27.8
  Top Layer w5: U1.W14@10196.33,7455.69 v1(10216.01,7436)
IO32: HDR2.71 U1.U12 | length 27.8
  Top Layer w5: U1.U12@10117.59,7534.43 v1(10137.27,7514.74)
IO33: HDR2.73 U1.AA17
IO34: HDR2.75 U1.Y16 | length 27.8
  Top Layer w5: U1.Y16@10275.07,7416.32 v1(10294.75,7396.63)
IO35: HDR2.77 U1.U13 | length 27.8
  Top Layer w5: U1.U13@10156.96,7534.43 v1(10176.64,7514.74)
JIOA0: HDR1.3 U1.A3
JIOA1: HDR1.5 U1.G1
JIOA2: HDR1.7 U1.E2
JIOA3: HDR1.9 U1.C4 | length 27.8
  Top Layer w5: v1(9782.94,8105.3) U1.C4@9802.63,8085.61
JIOB0: HDR1.83 U1.C22
JIOB1: HDR1.85 U1.G19 | length 27.8
  Top Layer w5: U1.G19@10393.18,7928.13 v1(10412.86,7947.82)
JIOB2: HDR1.87 U1.G20 | length 27.8
  Top Layer w5: U1.G20@10432.55,7928.13 v1(10452.23,7947.82)
JIOB3: HDR1.89 U1.H19 | length 27.8
  Top Layer w5: U1.H19@10393.18,7888.76 v1(10412.86,7908.45)
KBCLOCK: HDR1.22 U1.E4 | length 27.8
  Top Layer w5: v1(9782.94,8026.56) U1.E4@9802.63,8006.87
KBDATA: HDR1.24 U1.G3 | length 27.8
  Top Layer w5: v1(9743.57,7947.82) U1.G3@9763.26,7928.13
LCD_BCKL: HDR2.22 U1.W7 | length 27.8
  Top Layer w5: v1(9901.05,7436) U1.W7@9920.74,7455.69
LCD_E: HDR2.26 U1.M3 | length 27.8
  Top Layer w5: v1(9743.57,7711.59) U1.M3@9763.26,7731.28
LED0: HDR2.60 U1.V15 | length 67.2
  Top Layer w5: U1.V15@10235.7,7495.06 v1(10255.38,7475.37)
  Bottom Layer w5: HDR2.60@10861.68,6979.31 10861.68,7018.68
LED1: HDR2.62 U1.W16 | length 27.8
  Top Layer w5: U1.W16@10275.07,7455.69 v1(10294.75,7436)
LED2: HDR2.64 U1.AA19
LED3: HDR2.66 U1.V16 | length 27.8
  Top Layer w5: U1.V16@10275.07,7495.06 v1(10294.75,7475.37)
LED4: HDR2.68 U1.Y19 | length 27.8
  Top Layer w5: U1.Y19@10393.18,7416.32 v1(10412.86,7396.63)
LED5: HDR2.70 U1.L6 | length 27.8
  Top Layer w5: v1(9861.68,7790.34) U1.L6@9881.37,7770.65
LED6: HDR2.72 U1.V17 | length 27.8
  Top Layer w5: U1.V17@10314.44,7495.06 v1(10334.12,7475.37)
LED7: HDR2.74 U1.Y20 | length 27.8
  Top Layer w5: U1.Y20@10432.55,7416.32 v1(10452.23,7396.63)
MOUSECLOCK: HDR1.26 U1.C6 | length 27.8
  Top Layer w5: v1(9861.68,8105.3) U1.C6@9881.37,8085.61
MOUSEDATA: HDR1.28 U1.B6
NBLE0: U1.H21 U5.37
NBLE1: U1.J6 U5.36 | length 27.8
  Top Layer w5: v1(9861.68,7869.08) U1.J6@9881.37,7849.39
NBLE2: U1.J1 U5.35
NBLE3: U1.G22 U5.34
NCS0: U1.L21 U5.48
NCS1: U1.L4 U5.47 | length 27.8
  Top Layer w5: v1(9782.94,7790.34) U1.L4@9802.63,7770.65
NCS2: U1.L3 U5.46 | length 27.8
  Top Layer w5: v1(9743.57,7790.34) U1.L3@9763.26,7770.65
NCS3: U1.K20 U5.44 | length 27.8
  Top Layer w5: U1.K20@10432.55,7810.02 v1(10452.23,7829.71)
NCS4: U1.J22 U5.43
NCS5: U1.J21 U5.42
NDACK0: U1.H18 U5.147 | length 27.8
  Top Layer w5: U1.H18@10353.81,7888.76 v1(10373.49,7908.45)
NetC59_1: C59.1 R36.1 R37.2 | length 448
  Bottom Layer w5: R36.1@11349.87,7920.26 11365.62,7920.26 11406.39,7961.03 11406.39,7966.93 R37.2@11418.77,7979.31 11458.14,7939.94 11672.71,7939.94 11716.01,7896.63 C59.1@11735.7,7896.63
NetC60_1: C60.1 R44.1 R46.2 | length 458.3
  Bottom Layer w5: R44.1@11349.87,7873.01 R46.2@11428.61,7873.01 ; R46.2@11414.83,7888.76 11456.01,7929.94 11663.02,7929.94 11704.2,7888.76 11704.2,7869.07 11716.01,7857.26 C60.1@11735.7,7857.26
NetC61_1: C61.1 C63.1 C64.1 C65.1 D1.3 R59.2 U5.91 | length 864.6
  Top Layer w5: U5.91@11944.36,7857.26 11979.79,7857.26 11991.6,7845.45 v1(12007.35,7845.45)
  Bottom Layer w7.87: R59.2@11497.51,8227.34 11509.32,8215.53 D1.3@11509.32,8101.36 D1.3@11509.32,8099.39 ; D1.3@11508.33,8100.37 D1.3@11509.32,8099.39 ; C61.1@12003.41,7873.01 12007.35,7869.07 v1(12007.35,7845.45) ; C63.1@12007.35,7813.96 v1(12007.35,7845.45) ; D1.3@11509.32,8099.39 C65.1@11605.78,8002.93 C64.1@11755.38,8002.93 11842,8002.93 11991.6,7853.33 v1(12007.35,7845.45)
NetC61_2: C61.2 C63.2 C64.2 C65.2 U5.92 | length 706.5
  Top Layer w5: U5.92@11944.36,7873.01 11987.67,7873.01 11995.54,7865.14 12023.1,7865.14 v1(12042.78,7845.45)
  Bottom Layer w7.87: C65.2@11629.4,8121.04 C64.2@11755.38,8121.04 11767.19,8121.04 11790.82,8097.42 11790.82,8073.8 11936.48,7928.13 12007.35,7928.13 12042.78,7892.7 v1(12042.78,7845.45) C63.2@12042.78,7817.89
NetLED1_1: LED1.1 R5.2 | length 333.5
  Top Layer w7.87: LED1.1@11273.1,6546.24 11273.1,6497.03 11306.56,6463.56 11389.24,6463.56 11471.92,6546.24 R5.2@11509.32,6546.24
NetLED2_1: LED2.1 R16.1 | length 215.7
  Top Layer w7.87: R16.1@9899.08,6601.36 9971.92,6601.36 10027.04,6546.24 LED2.1@10092,6546.24
NetLED2_2: LED2.2 U2.4 | length 703.1
  Top Layer w7.87: U2.4@9521.13,6557.07 9571.33,6557.07 9649.08,6479.31 10121.52,6479.31 10149.08,6506.87 LED2.2@10149.08,6538.37
NetLED3_1: LED3.1 R58.2 | length 681.6
  Top Layer w7.87: R58.2@11298.69,9341.52 R58.2@11304.59,9341.52 v1(11306.56,9388.76) ; v1(11806.56,9589.55) LED3.1@11851.84,9589.55
  Mid-Layer 3 w5: v1(11306.56,9388.76) 11479.79,9561.99 11779,9561.99 v1(11806.56,9589.55)
NetP1_1: P1.1 P5.2 R58.1 R60.1 U6.1 | length 1745.1
  Top Layer w5: P1.1@10487.67,9955.69 10552.28,9891.07 10581.85,9891.07 P5.2@10630.02,9842.91 ; v1(11184.52,9341.52) 11227.82,9341.52 R58.1@11228.81,9340.53 ; U6.1@11507.35,9130.89 v1(11507.35,9180.1)
  Mid-Layer 1 w5: v1(11184.52,9341.52) 11345.93,9341.52 v1(11507.35,9180.1)
  Mid-Layer 2 w5: P1.1@10487.67,9955.69 10551.61,9891.74 10755.97,9891.74 10821.9,9825.82 10821.9,9712.01 11054.59,9479.31 11086.09,9479.31 11184.52,9380.89 v1(11184.52,9341.52)
  Bottom Layer w5: R60.1@11507.35,9148.6 v1(11507.35,9180.1)
NetP2_17: P2.17 R66.2 | length 774.4
  Mid-Layer 2 w5: P2.17@11003.81,9954.51 11050.66,9907.66 11050.66,9810.02 v1(11460.11,9400.57)
  Bottom Layer w5: R66.2@11460.11,9369.07 v1(11460.11,9400.57)
NetP2_19: P2.19 R67.2 | length 819.4
  Mid-Layer 2 w5: P2.19@10903.81,9954.51 10952.23,9906.08 10952.23,9821.83 11373.49,9400.57 v1(11412.86,9400.57)
  Bottom Layer w5: R67.2@11412.86,9369.07 v1(11412.86,9400.57)
NetR21_1: R21.1 U5.104 | length 84.6
  Top Layer w5: v3(11897.11,8061.99) U5.104@11944.36,8061.99
  Bottom Layer w5: v3(11897.11,8061.99) 11920.74,8085.61 R21.1@11924.67,8085.61
NetR22_1: R22.1 U5.99 | length 303.9
  Top Layer w5: v3(11834.12,8097.42) 11861.68,8069.86 11861.68,8010.81 11889.24,7983.25 U5.99@11944.36,7983.25
  Bottom Layer w5: v3(11834.12,8097.42) 11885.3,8046.24 R22.1@11924.67,8046.24
NetR23_1: R23.1 U5.98 | length 310.1
  Top Layer w5: v3(11834.12,8073.8) 11834.12,8018.68 11885.3,7967.5 U5.98@11944.36,7967.5
  Bottom Layer w5: v3(11834.12,8073.8) 11869.56,8038.37 11869.56,8030.49 11885.3,8014.74 R23.1@11928.61,8014.74
NetR25_1: R25.1 U5.127 | length 83.6
  Top Layer w5: v3(11897.11,8424.19) U5.127@11944.36,8424.19
  Bottom Layer w5: v3(11897.11,8424.19) 11908.93,8436 R25.1@11928.61,8436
